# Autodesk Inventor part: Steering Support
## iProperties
Length Units: 11269
Angle Units: 11279
Time Units: 11290
Mass Units: 11283
Shininess: 3
Angle Display Precision: 2
Document Length Units: 11269
Document Angle Units: 11279
Document Time Units: 11290
Document Mass Units: 11283
Document Length Units Precision: 3
Document Angle Units Precision: 2
Created: 2001-08
Part Number: Steering Support
Document SubType Name: Modeling
Designer: Martin Budgell
Density: 0.0
Volumn: 0.0
Area: 0.0
PropertySet Name: Model Information
Control State: 0
Master: False
Checked Out: False
Author: Martin Budgell
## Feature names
1. Extrusion1
2. Sweep1
3. Chamfer1
